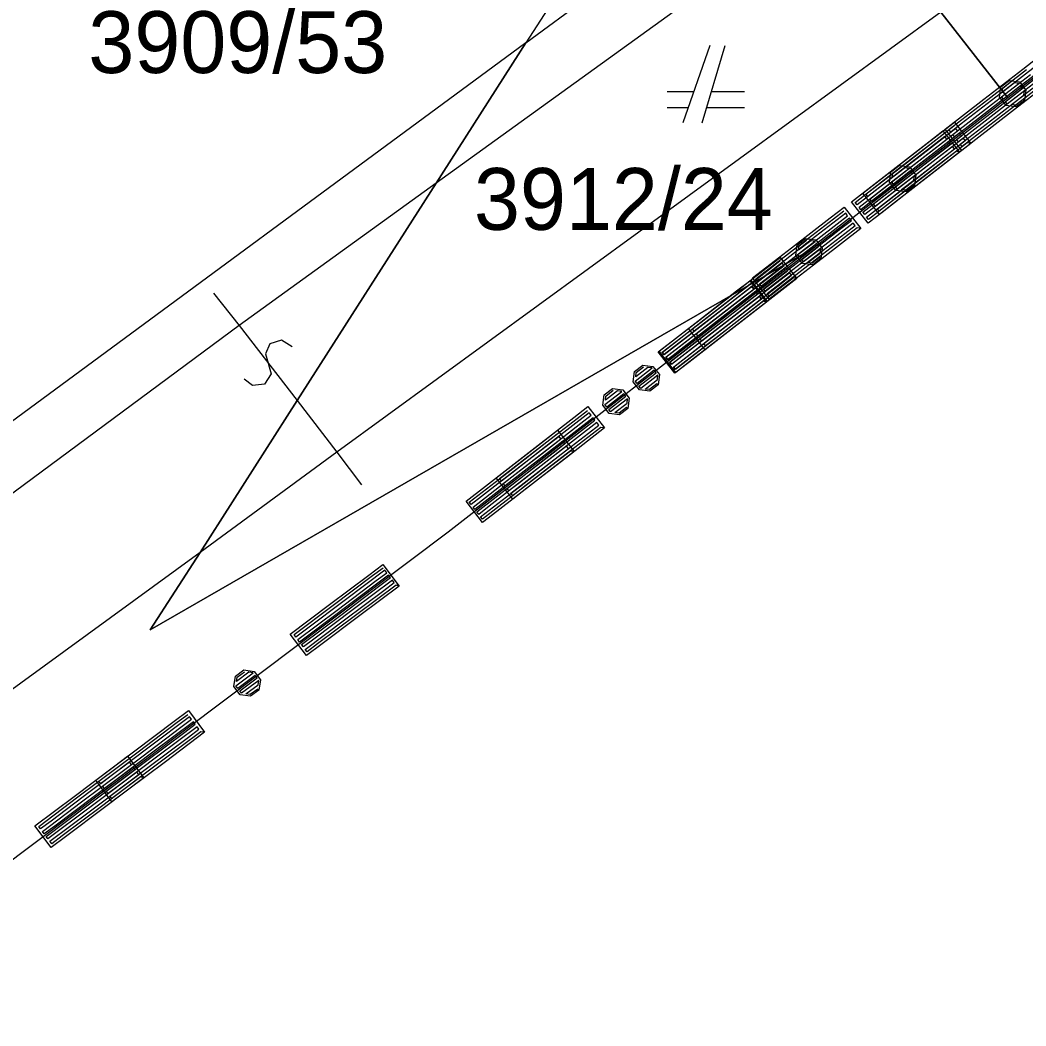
# Model space of a CAD drawing. Extents: x -266179 to -264727, y -1243225 to -1241702.
# Drawn here: x -265401.94 to -265375.91, y -1242993.93 to -1242967.89 of the extents above; entities that cross this region are included whole.
import ezdxf

# ---------------------------------------------------------------- set-up
doc = ezdxf.new("R2010")
doc.units = 0
for name, color, linetype in [('Vrstva 1', 7, 'Continuous'), ('Vrstva 19', 7, 'Continuous'), ('Vrstva 2', 7, 'Continuous'), ('Vrstva 21', 7, 'Continuous')]:
    doc.layers.add(name, color=color, linetype=linetype)

msp = doc.modelspace()

# ---------------------------------------------------------------- linework, layer by layer
at = {"layer": 'Vrstva 1'}
for p, q in [((-265383.72, -1242960.46), (-265388.85, -1242968.48)), ((-265376.38, -1242969.9), (-265378.11, -1242967.68)), ((-265378.11, -1242967.68), (-265376.38, -1242969.9)), ((-265373.95, -1242968.02), (-265376.38, -1242969.9)), ((-265388.85, -1242968.48), (-265403.6, -1242979.35)), ((-265391.17, -1242972.11), (-265388.85, -1242968.48)), ((-265388.85, -1242968.48), (-265391.17, -1242972.11)), ((-265384.09, -1242968.55), (-265384.79, -1242970.55)), ((-265384.29, -1242970.55), (-265383.69, -1242968.55)), ((-265384.51, -1242969.75), (-265385.19, -1242969.75)), ((-265383.19, -1242969.75), (-265384.05, -1242969.75)), ((-265376.38, -1242969.9), (-265381.38, -1242973.78)), ((-265385.19, -1242970.15), (-265384.65, -1242970.15)), ((-265384.17, -1242970.15), (-265383.19, -1242970.15)), ((-265394.77, -1242977.74), (-265391.17, -1242972.11)), ((-265391.17, -1242972.11), (-265394.77, -1242977.74)), ((-265381.38, -1242973.78), (-265398.57, -1242983.68)), ((-265398.57, -1242983.68), (-265381.38, -1242973.78)), ((-265381.38, -1242973.78), (-265390.86, -1242981.15)), ((-265397.28, -1242981.67), (-265394.77, -1242977.74)), ((-265394.77, -1242977.74), (-265397.28, -1242981.67)), ((-265390.86, -1242981.15), (-265407.86, -1242993.93)), ((-265398.57, -1242983.68), (-265397.28, -1242981.67)), ((-265397.28, -1242981.67), (-265398.57, -1242983.68))]:
    msp.add_line(p, q, dxfattribs=at)
at = {"layer": 'Vrstva 19'}
for p, q in [((-265373.95, -1242968.02), (-265376.38, -1242969.9)), ((-265376.38, -1242969.9), (-265381.38, -1242973.78)), ((-265381.38, -1242973.78), (-265390.86, -1242981.15)), ((-265390.86, -1242981.15), (-265407.86, -1242993.93))]:
    msp.add_line(p, q, dxfattribs=at)
for points in [[(-265375.199, -1242969.429), (-265376.203, -1242970.206), (-265377.208, -1242970.983), (-265377.572, -1242971.265), (-265378, -1242970.711), (-265376.996, -1242969.934), (-265375.991, -1242969.157), (-265375.627, -1242968.875)], [(-265375.575, -1242969.025), (-265376.579, -1242969.802), (-265377.584, -1242970.579), (-265377.853, -1242970.787), (-265377.902, -1242970.724), (-265376.897, -1242969.946), (-265375.893, -1242969.169)], [(-265375.477, -1242969.151), (-265376.482, -1242969.928), (-265377.486, -1242970.705), (-265377.755, -1242970.913), (-265377.804, -1242970.85), (-265376.799, -1242970.073), (-265375.795, -1242969.296)], [(-265375.379, -1242969.278), (-265376.384, -1242970.055), (-265377.388, -1242970.832), (-265377.657, -1242971.04), (-265377.706, -1242970.977), (-265376.702, -1242970.2), (-265375.697, -1242969.423)], [(-265375.281, -1242969.404), (-265376.286, -1242970.181), (-265377.29, -1242970.958), (-265377.559, -1242971.166), (-265377.608, -1242971.103), (-265376.604, -1242970.326), (-265375.599, -1242969.549)], [(-265375.946, -1242969.968), (-265376.159, -1242970.134), (-265376.426, -1242970.1), (-265376.591, -1242969.887), (-265376.558, -1242969.62), (-265376.345, -1242969.455), (-265376.078, -1242969.488), (-265375.912, -1242969.701), (-265375.946, -1242969.968), (-265375.978, -1242969.943), (-265376.168, -1242970.09), (-265376.28, -1242970.076), (-265375.964, -1242969.83), (-265375.95, -1242969.718), (-265376.392, -1242970.062), (-265376.441, -1242969.998), (-265375.999, -1242969.655), (-265376.048, -1242969.592), (-265376.49, -1242969.935), (-265376.54, -1242969.872), (-265376.097, -1242969.529), (-265376.21, -1242969.514), (-265376.525, -1242969.76), (-265376.511, -1242969.648), (-265376.322, -1242969.5)], [(-265377.333, -1242971.084), (-265378.336, -1242971.863), (-265379.339, -1242972.642), (-265379.702, -1242972.924), (-265380.132, -1242972.371), (-265379.129, -1242971.592), (-265378.126, -1242970.813), (-265377.763, -1242970.531), (-265377.333, -1242971.084), (-265377.431, -1242971.071), (-265378.434, -1242971.85), (-265379.437, -1242972.629), (-265379.706, -1242972.838), (-265379.755, -1242972.775), (-265378.752, -1242971.996), (-265377.749, -1242971.217), (-265377.48, -1242971.008), (-265377.53, -1242970.945), (-265378.533, -1242971.724), (-265379.535, -1242972.503), (-265379.804, -1242972.712), (-265379.853, -1242972.648), (-265378.85, -1242971.869), (-265377.847, -1242971.09), (-265377.579, -1242970.882), (-265377.628, -1242970.819), (-265378.631, -1242971.598), (-265379.634, -1242972.377), (-265379.902, -1242972.585), (-265379.951, -1242972.522), (-265378.948, -1242971.743), (-265377.945, -1242970.964), (-265377.677, -1242970.755), (-265377.726, -1242970.692), (-265378.729, -1242971.471), (-265379.732, -1242972.25), (-265380, -1242972.459), (-265380.049, -1242972.396), (-265379.046, -1242971.617), (-265378.043, -1242970.838), (-265377.775, -1242970.629)], [(-265377.628, -1242971.309), (-265378.631, -1242972.088), (-265379.634, -1242972.867), (-265379.997, -1242973.149), (-265380.427, -1242972.596), (-265379.424, -1242971.817), (-265378.421, -1242971.038), (-265378.058, -1242970.756), (-265377.628, -1242971.309), (-265377.711, -1242971.284), (-265378.714, -1242972.063), (-265379.717, -1242972.842), (-265379.985, -1242973.051), (-265380.034, -1242972.988), (-265379.031, -1242972.209), (-265378.028, -1242971.43), (-265377.76, -1242971.221), (-265377.809, -1242971.158), (-265378.812, -1242971.937), (-265379.815, -1242972.716), (-265380.083, -1242972.925), (-265380.132, -1242972.861), (-265379.129, -1242972.082), (-265378.126, -1242971.303), (-265377.858, -1242971.095), (-265377.907, -1242971.032), (-265378.91, -1242971.811), (-265379.913, -1242972.59), (-265380.181, -1242972.798), (-265380.23, -1242972.735), (-265379.227, -1242971.956), (-265378.225, -1242971.177), (-265377.956, -1242970.968), (-265378.005, -1242970.905), (-265379.008, -1242971.684), (-265380.011, -1242972.463), (-265380.28, -1242972.672), (-265380.329, -1242972.609), (-265379.326, -1242971.83), (-265378.323, -1242971.051), (-265378.054, -1242970.842)], [(-265378.792, -1242972.171), (-265379.006, -1242972.336), (-265379.273, -1242972.302), (-265379.438, -1242972.089), (-265379.404, -1242971.822), (-265379.19, -1242971.657), (-265378.924, -1242971.691), (-265378.758, -1242971.904), (-265378.792, -1242972.171), (-265378.825, -1242972.145), (-265379.015, -1242972.292), (-265379.127, -1242972.278), (-265378.81, -1242972.033), (-265378.796, -1242971.921), (-265379.239, -1242972.264), (-265379.288, -1242972.2), (-265378.845, -1242971.858), (-265378.894, -1242971.794), (-265379.337, -1242972.137), (-265379.386, -1242972.074), (-265378.943, -1242971.731), (-265379.055, -1242971.717), (-265379.372, -1242971.962), (-265379.357, -1242971.849), (-265379.167, -1242971.703)], [(-265380.182, -1242973.284), (-265381.187, -1242974.061), (-265382.191, -1242974.838), (-265382.555, -1242975.119), (-265382.983, -1242974.566), (-265381.979, -1242973.789), (-265380.974, -1242973.012), (-265380.61, -1242972.73), (-265380.182, -1242973.284), (-265380.28, -1242973.271), (-265381.285, -1242974.048), (-265382.289, -1242974.825), (-265382.558, -1242975.033), (-265382.607, -1242974.97), (-265381.603, -1242974.193), (-265380.598, -1242973.416), (-265380.329, -1242973.208), (-265380.378, -1242973.145), (-265381.383, -1242973.922), (-265382.387, -1242974.699), (-265382.656, -1242974.907), (-265382.705, -1242974.844), (-265381.7, -1242974.067), (-265380.696, -1242973.289), (-265380.427, -1242973.081), (-265380.476, -1242973.018), (-265381.48, -1242973.795), (-265382.485, -1242974.572), (-265382.754, -1242974.78), (-265382.803, -1242974.717), (-265381.798, -1242973.94), (-265380.794, -1242973.163), (-265380.525, -1242972.955), (-265380.574, -1242972.892), (-265381.578, -1242973.669), (-265382.583, -1242974.446), (-265382.852, -1242974.654), (-265382.901, -1242974.59), (-265381.896, -1242973.813), (-265380.892, -1242973.036), (-265380.623, -1242972.828)], [(-265381.216, -1242974.058), (-265381.429, -1242974.224), (-265381.696, -1242974.19), (-265381.862, -1242973.977), (-265381.828, -1242973.71), (-265381.615, -1242973.545), (-265381.348, -1242973.578), (-265381.183, -1242973.791), (-265381.216, -1242974.058), (-265381.249, -1242974.032), (-265381.438, -1242974.18), (-265381.55, -1242974.166), (-265381.235, -1242973.92), (-265381.22, -1242973.808), (-265381.663, -1242974.151), (-265381.712, -1242974.088), (-265381.27, -1242973.745), (-265381.319, -1242973.682), (-265381.761, -1242974.025), (-265381.81, -1242973.962), (-265381.368, -1242973.618), (-265381.48, -1242973.604), (-265381.796, -1242973.85), (-265381.782, -1242973.737), (-265381.592, -1242973.59)], [(-265381.841, -1242974.584), (-265382.844, -1242975.363), (-265383.847, -1242976.143), (-265384.211, -1242976.425), (-265384.64, -1242975.872), (-265383.637, -1242975.093), (-265382.634, -1242974.314), (-265382.271, -1242974.032), (-265381.841, -1242974.584), (-265381.924, -1242974.56), (-265382.927, -1242975.339), (-265383.93, -1242976.118), (-265384.198, -1242976.327), (-265384.247, -1242976.263), (-265383.244, -1242975.484), (-265382.241, -1242974.705), (-265381.973, -1242974.497), (-265382.022, -1242974.433), (-265383.025, -1242975.213), (-265384.028, -1242975.992), (-265384.296, -1242976.2), (-265384.345, -1242976.137), (-265383.342, -1242975.358), (-265382.339, -1242974.579), (-265382.071, -1242974.37), (-265382.12, -1242974.307), (-265383.123, -1242975.086), (-265384.126, -1242975.865), (-265384.395, -1242976.074), (-265384.444, -1242976.011), (-265383.441, -1242975.232), (-265382.438, -1242974.452), (-265382.169, -1242974.244), (-265382.218, -1242974.181), (-265383.221, -1242974.96), (-265384.224, -1242975.739), (-265384.493, -1242975.947), (-265384.542, -1242975.884), (-265383.539, -1242975.105), (-265382.536, -1242974.326), (-265382.267, -1242974.118)], [(-265382.625, -1242975.193), (-265383.628, -1242975.972), (-265384.631, -1242976.752), (-265384.994, -1242977.034), (-265385.423, -1242976.481), (-265384.42, -1242975.702), (-265383.417, -1242974.923), (-265383.054, -1242974.641), (-265382.625, -1242975.193), (-265382.707, -1242975.169), (-265383.71, -1242975.948), (-265384.713, -1242976.727), (-265384.982, -1242976.936), (-265385.031, -1242976.872), (-265384.028, -1242976.093), (-265383.025, -1242975.314), (-265382.756, -1242975.106), (-265382.805, -1242975.042), (-265383.808, -1242975.822), (-265384.811, -1242976.601), (-265385.08, -1242976.809), (-265385.129, -1242976.746), (-265384.126, -1242975.967), (-265383.123, -1242975.188), (-265382.854, -1242974.979), (-265382.903, -1242974.916), (-265383.906, -1242975.695), (-265384.909, -1242976.474), (-265385.178, -1242976.683), (-265385.227, -1242976.62), (-265384.224, -1242975.841), (-265383.221, -1242975.061), (-265382.952, -1242974.853), (-265383.002, -1242974.79), (-265384.005, -1242975.569), (-265385.007, -1242976.348), (-265385.276, -1242976.556), (-265385.325, -1242976.493), (-265384.322, -1242975.714), (-265383.319, -1242974.935), (-265383.051, -1242974.727)], [(-265382.604, -1242975.174), (-265383.607, -1242975.953), (-265384.61, -1242976.732), (-265384.973, -1242977.014), (-265385.402, -1242976.461), (-265384.399, -1242975.682), (-265383.396, -1242974.903), (-265383.033, -1242974.621), (-265382.604, -1242975.174), (-265382.702, -1242975.161), (-265383.705, -1242975.94), (-265384.708, -1242976.719), (-265384.976, -1242976.928), (-265385.025, -1242976.865), (-265384.022, -1242976.086), (-265383.019, -1242975.307), (-265382.751, -1242975.098), (-265382.8, -1242975.035), (-265383.803, -1242975.814), (-265384.806, -1242976.593), (-265385.074, -1242976.802), (-265385.123, -1242976.738), (-265384.121, -1242975.959), (-265383.118, -1242975.18), (-265382.849, -1242974.972), (-265382.898, -1242974.908), (-265383.901, -1242975.688), (-265384.904, -1242976.467), (-265385.173, -1242976.675), (-265385.222, -1242976.612), (-265384.219, -1242975.833), (-265383.216, -1242975.054), (-265382.947, -1242974.845), (-265382.996, -1242974.782), (-265383.999, -1242975.561), (-265385.002, -1242976.34), (-265385.271, -1242976.549), (-265385.32, -1242976.486), (-265384.317, -1242975.707), (-265383.314, -1242974.927), (-265383.045, -1242974.719)], [(-265385.429, -1242977.333), (-265385.643, -1242977.499), (-265385.909, -1242977.466), (-265386.075, -1242977.252), (-265386.041, -1242976.986), (-265385.828, -1242976.82), (-265385.562, -1242976.854), (-265385.396, -1242977.067), (-265385.429, -1242977.333), (-265385.462, -1242977.308), (-265385.651, -1242977.455), (-265385.764, -1242977.441), (-265385.448, -1242977.196), (-265385.434, -1242977.084), (-265385.876, -1242977.427), (-265385.925, -1242977.364), (-265385.483, -1242977.02), (-265385.532, -1242976.957), (-265385.974, -1242977.301), (-265386.023, -1242977.238), (-265385.581, -1242976.894), (-265385.693, -1242976.88), (-265386.009, -1242977.125), (-265385.995, -1242977.013), (-265385.805, -1242976.866)], [(-265386.213, -1242977.942), (-265386.426, -1242978.108), (-265386.693, -1242978.075), (-265386.858, -1242977.861), (-265386.825, -1242977.595), (-265386.611, -1242977.429), (-265386.345, -1242977.463), (-265386.179, -1242977.676), (-265386.213, -1242977.942), (-265386.245, -1242977.917), (-265386.435, -1242978.064), (-265386.547, -1242978.05), (-265386.231, -1242977.805), (-265386.217, -1242977.692), (-265386.659, -1242978.036), (-265386.708, -1242977.973), (-265386.266, -1242977.629), (-265386.315, -1242977.566), (-265386.757, -1242977.91), (-265386.806, -1242977.846), (-265386.364, -1242977.503), (-265386.476, -1242977.489), (-265386.792, -1242977.734), (-265386.778, -1242977.622), (-265386.589, -1242977.475)], [(-265386.817, -1242978.449), (-265387.82, -1242979.228), (-265388.823, -1242980.007), (-265389.186, -1242980.289), (-265389.615, -1242979.737), (-265388.612, -1242978.958), (-265387.609, -1242978.178), (-265387.246, -1242977.896), (-265386.817, -1242978.449), (-265386.915, -1242978.437), (-265387.918, -1242979.216), (-265388.921, -1242979.995), (-265389.189, -1242980.203), (-265389.238, -1242980.14), (-265388.235, -1242979.361), (-265387.233, -1242978.582), (-265386.964, -1242978.374), (-265387.013, -1242978.31), (-265388.016, -1242979.089), (-265389.019, -1242979.869), (-265389.288, -1242980.077), (-265389.337, -1242980.014), (-265388.334, -1242979.235), (-265387.331, -1242978.456), (-265387.062, -1242978.247), (-265387.111, -1242978.184), (-265388.114, -1242978.963), (-265389.117, -1242979.742), (-265389.386, -1242979.951), (-265389.435, -1242979.888), (-265388.432, -1242979.108), (-265387.429, -1242978.329), (-265387.16, -1242978.121), (-265387.209, -1242978.058), (-265388.212, -1242978.837), (-265389.215, -1242979.616), (-265389.484, -1242979.824), (-265389.533, -1242979.761), (-265388.53, -1242978.982), (-265387.527, -1242978.203), (-265387.258, -1242977.994)], [(-265387.6, -1242979.058), (-265388.603, -1242979.837), (-265389.606, -1242980.616), (-265389.969, -1242980.898), (-265390.399, -1242980.346), (-265389.396, -1242979.567), (-265388.393, -1242978.787), (-265388.029, -1242978.505), (-265387.6, -1242979.058), (-265387.698, -1242979.046), (-265388.701, -1242979.825), (-265389.704, -1242980.604), (-265389.973, -1242980.812), (-265390.022, -1242980.749), (-265389.019, -1242979.97), (-265388.016, -1242979.191), (-265387.747, -1242978.983), (-265387.796, -1242978.919), (-265388.799, -1242979.698), (-265389.802, -1242980.478), (-265390.071, -1242980.686), (-265390.12, -1242980.623), (-265389.117, -1242979.844), (-265388.114, -1242979.065), (-265387.845, -1242978.856), (-265387.895, -1242978.793), (-265388.898, -1242979.572), (-265389.901, -1242980.351), (-265390.169, -1242980.56), (-265390.218, -1242980.497), (-265389.215, -1242979.717), (-265388.212, -1242978.938), (-265387.944, -1242978.73), (-265387.993, -1242978.667), (-265388.996, -1242979.446), (-265389.999, -1242980.225), (-265390.267, -1242980.433), (-265390.316, -1242980.37), (-265389.313, -1242979.591), (-265388.31, -1242978.812), (-265388.042, -1242978.603)], [(-265392.128, -1242982.542), (-265393.143, -1242983.305), (-265394.158, -1242984.068), (-265394.526, -1242984.344), (-265394.947, -1242983.785), (-265393.931, -1242983.022), (-265392.916, -1242982.259), (-265392.548, -1242981.983), (-265392.128, -1242982.542), (-265392.21, -1242982.516), (-265393.225, -1242983.279), (-265394.241, -1242984.042), (-265394.512, -1242984.246), (-265394.56, -1242984.183), (-265393.545, -1242983.42), (-265392.53, -1242982.657), (-265392.258, -1242982.452), (-265392.306, -1242982.388), (-265393.321, -1242983.151), (-265394.337, -1242983.914), (-265394.608, -1242984.119), (-265394.657, -1242984.055), (-265393.641, -1242983.292), (-265392.626, -1242982.529), (-265392.354, -1242982.325), (-265392.402, -1242982.261), (-265393.417, -1242983.023), (-265394.433, -1242983.786), (-265394.705, -1242983.991), (-265394.753, -1242983.927), (-265393.737, -1242983.164), (-265392.722, -1242982.401), (-265392.45, -1242982.197), (-265392.498, -1242982.133), (-265393.514, -1242982.896), (-265394.529, -1242983.658), (-265394.801, -1242983.863), (-265394.849, -1242983.799), (-265393.833, -1242983.036), (-265392.818, -1242982.273), (-265392.546, -1242982.069)], [(-265395.759, -1242985.234), (-265395.975, -1242985.396), (-265396.241, -1242985.358), (-265396.404, -1242985.142), (-265396.366, -1242984.876), (-265396.15, -1242984.714), (-265395.884, -1242984.752), (-265395.722, -1242984.968), (-265395.759, -1242985.234), (-265395.791, -1242985.208), (-265395.983, -1242985.352), (-265396.095, -1242985.336), (-265395.776, -1242985.096), (-265395.76, -1242984.984), (-265396.207, -1242985.32), (-265396.255, -1242985.256), (-265395.808, -1242984.92), (-265395.856, -1242984.856), (-265396.303, -1242985.192), (-265396.352, -1242985.128), (-265395.904, -1242984.792), (-265396.016, -1242984.776), (-265396.336, -1242985.016), (-265396.32, -1242984.904), (-265396.128, -1242984.76)], [(-265397.164, -1242986.327), (-265398.18, -1242987.09), (-265399.195, -1242987.853), (-265399.563, -1242988.129), (-265399.983, -1242987.569), (-265398.968, -1242986.807), (-265397.953, -1242986.044), (-265397.585, -1242985.767), (-265397.164, -1242986.327), (-265397.262, -1242986.313), (-265398.278, -1242987.076), (-265399.293, -1242987.839), (-265399.565, -1242988.043), (-265399.613, -1242987.979), (-265398.598, -1242987.216), (-265397.582, -1242986.453), (-265397.311, -1242986.249), (-265397.359, -1242986.185), (-265398.374, -1242986.948), (-265399.389, -1242987.711), (-265399.661, -1242987.915), (-265399.709, -1242987.851), (-265398.694, -1242987.088), (-265397.678, -1242986.325), (-265397.407, -1242986.121), (-265397.455, -1242986.057), (-265398.47, -1242986.82), (-265399.485, -1242987.583), (-265399.757, -1242987.787), (-265399.805, -1242987.723), (-265398.79, -1242986.96), (-265397.775, -1242986.197), (-265397.503, -1242985.993), (-265397.551, -1242985.929), (-265398.566, -1242986.692), (-265399.581, -1242987.455), (-265399.853, -1242987.659), (-265399.901, -1242987.595), (-265398.886, -1242986.832), (-265397.871, -1242986.07), (-265397.599, -1242985.865)], [(-265398.737, -1242987.511), (-265399.752, -1242988.273), (-265400.767, -1242989.036), (-265401.135, -1242989.313), (-265401.556, -1242988.753), (-265400.54, -1242987.99), (-265399.525, -1242987.227), (-265399.157, -1242986.951), (-265398.737, -1242987.511), (-265398.819, -1242987.485), (-265399.834, -1242988.248), (-265400.849, -1242989.01), (-265401.121, -1242989.215), (-265401.169, -1242989.151), (-265400.154, -1242988.388), (-265399.139, -1242987.625), (-265398.867, -1242987.421), (-265398.915, -1242987.357), (-265399.93, -1242988.12), (-265400.945, -1242988.883), (-265401.217, -1242989.087), (-265401.265, -1242989.023), (-265400.25, -1242988.26), (-265399.235, -1242987.497), (-265398.963, -1242987.293), (-265399.011, -1242987.229), (-265400.026, -1242987.992), (-265401.042, -1242988.755), (-265401.313, -1242988.959), (-265401.361, -1242988.895), (-265400.346, -1242988.132), (-265399.331, -1242987.369), (-265399.059, -1242987.165), (-265399.107, -1242987.101), (-265400.122, -1242987.864), (-265401.138, -1242988.627), (-265401.409, -1242988.831), (-265401.458, -1242988.767), (-265400.442, -1242988.004), (-265399.427, -1242987.241), (-265399.155, -1242987.037)]]:
    msp.add_lwpolyline(points, dxfattribs=at)
at = {"layer": 'Vrstva 2'}
for p, q in [((-265388.85, -1242968.48), (-265381.63, -1242963.15)), ((-265380.6, -1242964.47), (-265391.17, -1242972.11)), ((-265378.11, -1242967.68), (-265393.74, -1242979.08)), ((-265391.17, -1242972.11), (-265396.27, -1242975.8)), ((-265396.93, -1242974.96), (-265396.27, -1242975.8)), ((-265396.27, -1242975.8), (-265412.54, -1242987.85)), ((-265396.27, -1242975.8), (-265394.77, -1242977.74)), ((-265394.77, -1242977.74), (-265393.74, -1242979.08)), ((-265393.74, -1242979.08), (-265397.28, -1242981.67)), ((-265393.74, -1242979.08), (-265393.1, -1242979.92)), ((-265397.28, -1242981.67), (-265410.05, -1242990.99))]:
    msp.add_line(p, q, dxfattribs=at)
msp.add_lwpolyline([(-265394.896, -1242976.351), (-265395.173, -1242976.173), (-265395.478, -1242976.269), (-265395.59, -1242976.533), (-265395.442, -1242977.051), (-265395.618, -1242977.314), (-265395.929, -1242977.352), (-265396.144, -1242977.189)], dxfattribs=at)
at = {"layer": 'Vrstva 21'}
for p, q in [((-265373.95, -1242968.02), (-265376.38, -1242969.9)), ((-265376.38, -1242969.9), (-265381.38, -1242973.78)), ((-265381.38, -1242973.78), (-265390.86, -1242981.15)), ((-265390.86, -1242981.15), (-265407.86, -1242993.93))]:
    msp.add_line(p, q, dxfattribs=at)

# ---------------------------------------------------------------- texts
at = {"layer": 'Vrstva 1'}
for s, p in [('3909/53', (-265400.173, -1242969.26)), ('3912/24', (-265390.194, -1242973.32))]:
    msp.add_text(s, height=1.6, dxfattribs=at).set_placement(p)

doc.saveas('drawing.dxf')
